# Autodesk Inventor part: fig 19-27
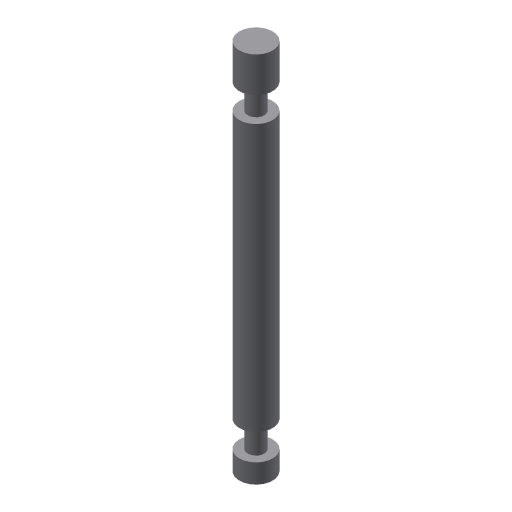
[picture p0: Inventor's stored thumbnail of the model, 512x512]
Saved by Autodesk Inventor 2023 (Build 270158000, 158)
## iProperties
Created: 2013-07
Part Number: fig 19-27
Material: Generic
Document SubType Name: Modeling
Designer: CADCIM
Density: 1 g/cm^3
Appearance: Default
Author: CADCIM
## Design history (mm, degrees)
sketch "Sketch3"
  geometry: L1 (0, 19.325)-(1.664, 19.325); L2 (1.664, 19.325)-(1.664, 15.806); L3 (1.664, 15.806)-(0.832, 15.806); L4 (0.832, 15.806)-(0.832, 13.31); L5 (0.832, 13.31)-(1.664, 13.31); L6 (1.664, 13.31)-(1.664, -13.31); L7 (1.664, -13.31)-(0.832, -13.31); L8 (0.832, -13.31)-(0.832, -15.934); L9 (0.832, -15.934)-(1.664, -15.934); L10 (1.664, -15.934)-(1.664, -17.853); L11 (1.664, -17.853)-(0, -17.853); L12 (0, -17.853)-(0, 19.325); 1 further point
  constraints: 24 end point, 8 perpendicular, 6 point on line, 1 horizontal
revolve "Revolution1" sketch "Sketch3" stored, may be unused: angle "d8" = 90 deg
body "Solid2"
